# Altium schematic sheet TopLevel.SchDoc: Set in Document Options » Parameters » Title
size A4; Author: Set in Document Options » Parameters » Author + Contact info
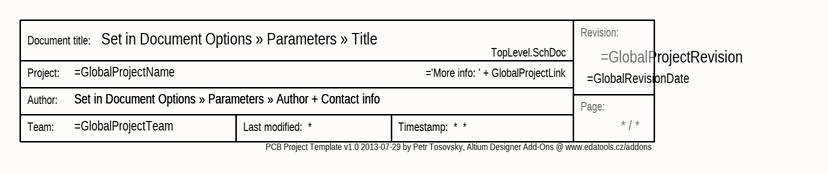
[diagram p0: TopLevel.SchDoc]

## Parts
Stamp  Stamp  (value not drawn)  (graphical)

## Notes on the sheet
- PCB Project Template v1.0 2013-07-29 by Petr Tosovsky, Altium Designer Add-Ons @ www.edatools.cz/addons <http://www.edatools.cz/addons>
